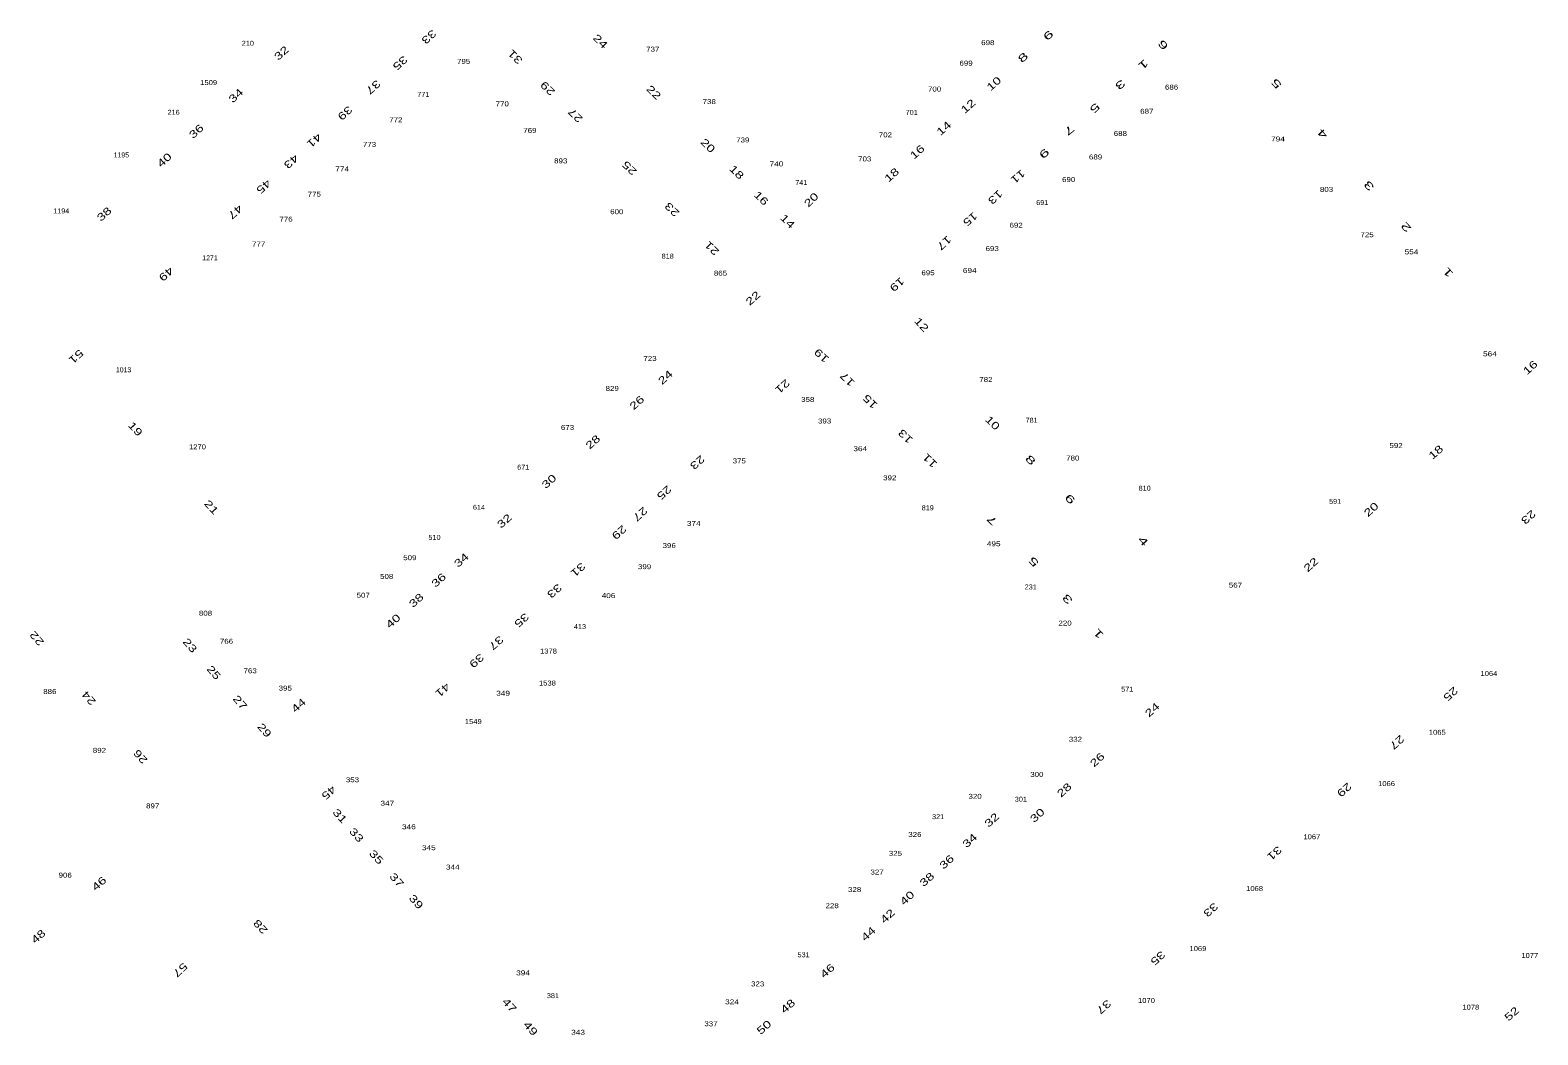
# Model space of a CAD drawing. Extents: x -828673 to -815583, y -1077737 to -1063807.
# Drawn here: x -819544.8 to -819239.5, y -1069308.8 to -1069105.5 of the extents above; entities that cross this region are included whole.
import ezdxf
from ezdxf.enums import TextEntityAlignment as Align

# ---------------------------------------------------------------- set-up
doc = ezdxf.new("R2010")
doc.units = 0
doc.header["$LTSCALE"] = 0.4
doc.layers.add('1', color=7, linetype='Continuous')
doc.layers.add('2', color=7, linetype='Continuous')

msp = doc.modelspace()

# ---------------------------------------------------------------- texts
at = {"layer": '1'}
for s, width, p in [('210', 1.1, (-819500.706, -1069108.652)), ('698', 1.2, (-819350.9, -1069108.522)), ('795', 1.2, (-819457.015, -1069112.317)), ('737', 1.2, (-819418.728, -1069109.841)), ('699', 1.2, (-819355.307, -1069112.674)), ('1509', 1.15, (-819508.639, -1069116.6)), ('700', 1.2, (-819361.669, -1069117.919)), ('686', 1.2, (-819313.692, -1069117.524)), ('771', 1.1, (-819465.18, -1069118.996)), ('770', 1.2, (-819449.199, -1069120.902)), ('738', 1.2, (-819407.298, -1069120.455)), ('216', 1.1, (-819515.726, -1069122.614)), ('772', 1.2, (-819470.741, -1069124.129)), ('701', 1.1, (-819366.311, -1069122.639)), ('687', 1.2, (-819318.711, -1069122.414)), ('769', 1.2, (-819443.605, -1069126.287)), ('702', 1.2, (-819371.637, -1069127.181)), ('688', 1.2, (-819324.064, -1069126.904)), ('773', 1.2, (-819476.07, -1069129.117)), ('739', 1.2, (-819400.501, -1069128.22)), ('794', 1.25, (-819292.15, -1069128.019)), ('1195', 1.05, (-819526.311, -1069131.255)), ('893', 1.2, (-819437.357, -1069132.45)), ('740', 1.25, (-819393.682, -1069133.057)), ('703', 1.2, (-819375.822, -1069132.053)), ('689', 1.2, (-819329.083, -1069131.66)), ('774', 1.25, (-819481.611, -1069134.077)), ('741', 1.1, (-819388.661, -1069136.838)), ('690', 1.2, (-819334.526, -1069136.227)), ('775', 1.2, (-819487.249, -1069139.182)), ('803', 1.2, (-819282.317, -1069138.219)), ('1194', 1.1, (-819538.478, -1069142.581)), ('600', 1.2, (-819426.009, -1069142.742)), ('691', 1.1, (-819339.878, -1069140.884)), ('776', 1.2, (-819492.975, -1069144.249)), ('692', 1.2, (-819345.164, -1069145.474)), ('725', 1.2, (-819274.121, -1069147.392)), ('1271', 1.05, (-819508.369, -1069152.082)), ('777', 1.2, (-819498.515, -1069149.284)), ('818', 1.1, (-819415.705, -1069151.741)), ('693', 1.2, (-819350.017, -1069150.197)), ('554', 1.25, (-819265.122, -1069150.858)), ('865', 1.2, (-819405.022, -1069155.175)), ('695', 1.2, (-819363.005, -1069155.103)), ('694', 1.25, (-819354.561, -1069154.637)), ('723', 1.2, (-819419.286, -1069172.445)), ('564', 1.25, (-819249.248, -1069171.499)), ('1013', 1.05, (-819525.868, -1069174.736)), ('829', 1.2, (-819426.936, -1069178.499)), ('782', 1.2, (-819351.279, -1069176.694)), ('358', 1.2, (-819387.35, -1069180.733)), ('393', 1.2, (-819383.941, -1069185.098)), ('781', 1.1, (-819342.037, -1069184.943)), ('673', 1.2, (-819435.977, -1069186.404)), ('1270', 1.15, (-819510.897, -1069190.316)), ('364', 1.25, (-819376.725, -1069190.701)), ('592', 1.2, (-819268.246, -1069190.071)), ('671', 1.1, (-819444.954, -1069194.447)), ('375', 1.2, (-819401.216, -1069193.173)), ('780', 1.2, (-819333.693, -1069192.593)), ('392', 1.2, (-819370.753, -1069196.594)), ('810', 1.1, (-819319.144, -1069198.693)), ('614', 1.1, (-819453.916, -1069202.565)), ('819', 1.1, (-819363.063, -1069202.678)), ('591', 1.1, (-819280.583, -1069201.357)), ('374', 1.25, (-819410.433, -1069205.832)), ('510', 1.1, (-819462.919, -1069208.651)), ('495', 1.25, (-819349.712, -1069209.944)), ('509', 1.2, (-819467.904, -1069212.763)), ('396', 1.2, (-819415.396, -1069210.306)), ('399', 1.2, (-819420.383, -1069214.584)), ('508', 1.2, (-819472.597, -1069216.556)), ('231', 1.1, (-819342.217, -1069218.688)), ('567', 1.2, (-819300.764, -1069218.329)), ('507', 1.2, (-819477.343, -1069220.35)), ('406', 1.25, (-819427.682, -1069220.433)), ('808', 1.2, (-819509.273, -1069223.997)), ('413', 1.1, (-819433.463, -1069226.708)), ('220', 1.2, (-819335.264, -1069225.999)), ('766', 1.2, (-819505.031, -1069229.674)), ('1378', 1.15, (-819439.842, -1069231.662)), ('763', 1.2, (-819500.234, -1069235.66)), ('1064', 1.15, (-819249.447, -1069236.205)), ('886', 1.2, (-819540.788, -1069239.847)), ('395', 1.2, (-819493.129, -1069239.162)), ('349', 1.25, (-819449.026, -1069240.193)), ('1538', 1.15, (-819440.054, -1069238.131)), ('571', 1.1, (-819322.672, -1069239.378)), ('1549', 1.15, (-819455.07, -1069245.928)), ('332', 1.2, (-819333.165, -1069249.505)), ('1065', 1.15, (-819259.896, -1069248.098)), ('892', 1.2, (-819530.75, -1069251.753)), ('353', 1.2, (-819479.525, -1069257.707)), ('300', 1.2, (-819340.964, -1069256.625)), ('1066', 1.15, (-819270.178, -1069258.477)), ('320', 1.2, (-819353.47, -1069261.062)), ('301', 1.1, (-819344.209, -1069261.645)), ('897', 1.2, (-819519.965, -1069262.993)), ('347', 1.25, (-819472.462, -1069262.454)), ('346', 1.25, (-819468.099, -1069267.229)), ('321', 1.1, (-819360.967, -1069265.176)), ('326', 1.2, (-819365.657, -1069268.777)), ('1067', 1.15, (-819285.299, -1069269.24)), ('345', 1.25, (-819464.064, -1069271.457)), ('325', 1.2, (-819369.611, -1069272.597)), ('906', 1.2, (-819537.684, -1069277.014)), ('344', 1.25, (-819459.216, -1069275.371)), ('327', 1.2, (-819373.32, -1069276.389)), ('328', 1.2, (-819377.863, -1069279.919)), ('1068', 1.15, (-819296.889, -1069279.722)), ('228', 1.2, (-819382.417, -1069283.193)), ('1069', 1.15, (-819308.365, -1069291.872)), ('531', 1.1, (-819388.198, -1069293.124)), ('1077', 1.15, (-819241.178, -1069293.275)), ('394', 1.25, (-819444.993, -1069296.789)), ('381', 1.1, (-819438.939, -1069301.4)), ('323', 1.2, (-819397.484, -1069299.021)), ('324', 1.25, (-819402.693, -1069302.65)), ('1070', 1.15, (-819318.776, -1069302.379)), ('1078', 1.15, (-819253.116, -1069303.73)), ('337', 1.2, (-819406.943, -1069307.088)), ('343', 1.25, (-819433.846, -1069308.81))]:
    msp.add_text(s, height=1, dxfattribs=dict(at, width=width)).set_placement(p, align=Align.CENTER)
at = {"layer": '2'}
for s, rotation, width, p in [('33', 222.205, 1.4, (-819464.5367, -1069106.3148)), ('24', 315.75, 1.4, (-819429.8553, -1069108.2929)), ('6', 41.825, 1.75, (-819338.1606, -1069107.1071)), ('6', 131.725, 1.75, (-819314.8655, -1069107.9997)), ('32', 42.334, 1.4, (-819493.3941, -1069110.677)), ('35', 222.177, 1.4, (-819470.3694, -1069111.5945)), ('31', 135.298, 1.4, (-819446.0509, -1069110.3945)), ('8', 41.987, 1.75, (-819343.2842, -1069111.5718)), ('1', 222, 1.75, (-819319.8927, -1069111.8994)), ('34', 42.713, 1.4, (-819502.6212, -1069119.2838)), ('37', 222.176, 1.4, (-819475.8224, -1069116.4825)), ('29', 136.01, 1.4, (-819439.4921, -1069116.7487)), ('22', 315.822, 1.4, (-819419.0507, -1069118.6198)), ('10', 41.781, 1.4, (-819349.1782, -1069116.8682)), ('3', 220.752, 1.75, (-819324.5624, -1069115.9774)), ('5', 132.373, 1.75, (-819291.9297, -1069115.823)), ('12', 41.653, 1.4, (-819354.392, -1069121.4458)), ('5', 223.476, 1.75, (-819329.7385, -1069120.7226)), ('39', 222.162, 1.4, (-819481.5216, -1069121.7351)), ('27', 135.745, 1.4, (-819433.8796, -1069122.22)), ('36', 42.096, 1.4, (-819510.6413, -1069126.5233)), ('41', 222.202, 1.4, (-819487.7647, -1069127.2737)), ('14', 41.875, 1.4, (-819359.3126, -1069125.9081)), ('7', 220.045, 1.75, (-819334.904, -1069125.1842)), ('4', 132.265, 1.75, (-819282.6026, -1069125.9794)), ('20', 315.69, 1.4, (-819408.0784, -1069129.3871)), ('16', 42.163, 1.4, (-819364.6914, -1069130.7019)), ('9', 223.307, 1.75, (-819340.0016, -1069129.9107)), ('40', 42.174, 1.4, (-819517.1035, -1069132.3266)), ('43', 222.17, 1.4, (-819492.4185, -1069131.5453)), ('25', 135.669, 1.4, (-819422.9284, -1069132.8843)), ('45', 222.129, 1.4, (-819497.9874, -1069136.6126)), ('18', 315.67, 1.4, (-819402.2656, -1069134.7677)), ('18', 41.696, 1.4, (-819369.8639, -1069135.3501)), ('11', 220.426, 1.35, (-819345.2607, -1069134.5673)), ('16', 315.718, 1.4, (-819397.2996, -1069140.0358)), ('20', 44.904, 1.4, (-819386.1204, -1069140.3621)), ('13', 223.118, 1.4, (-819349.8739, -1069138.7518)), ('3', 132.545, 1.75, (-819273.1836, -1069136.5071)), ('38', 42.263, 1.4, (-819529.2844, -1069143.259)), ('47', 222.218, 1.4, (-819503.7385, -1069141.7332)), ('23', 135.98, 1.4, (-819414.3213, -1069141.2753)), ('14', 315.798, 1.4, (-819391.9474, -1069144.704)), ('15', 220.727, 1.35, (-819354.9387, -1069143.1858)), ('2', 132.34, 1.75, (-819265.6622, -1069144.8756)), ('17', 222.872, 1.4, (-819360.2372, -1069148.0128)), ('21', 135.71, 1.4, (-819406.2583, -1069149.106)), ('49', 221.844, 1.4, (-819517.7292, -1069154.3125)), ('1', 132.358, 1.75, (-819257.1839, -1069154.0423)), ('19', 221.566, 1.4, (-819369.7509, -1069156.4148)), ('22', 41.944, 1.4, (-819397.9428, -1069160.2926)), ('12', 312.243, 1.4, (-819364.8781, -1069165.5743)), ('51', 222.715, 1.4, (-819535.9697, -1069171.0173)), ('19', 137.273, 1.4, (-819384.0641, -1069170.8199)), ('16', 42.155, 1.4, (-819240.5834, -1069174.3241)), ('24', 41.835, 1.4, (-819415.6747, -1069176.3097)), ('17', 135.668, 1.4, (-819378.8214, -1069175.6332)), ('21', 222.023, 1.4, (-819392.9589, -1069177.0532)), ('26', 41.991, 1.4, (-819421.4468, -1069181.4408)), ('15', 135.44, 1.4, (-819374.1948, -1069180.1441)), ('10', 315.665, 1.4, (-819350.4636, -1069185.5148)), ('19', 312.746, 1.4, (-819524.0183, -1069186.6989)), ('28', 41.796, 1.4, (-819430.3554, -1069189.4008)), ('13', 135.948, 1.4, (-819367.0525, -1069187.1859)), ('18', 41.489, 1.4, (-819259.7034, -1069191.4664)), ('23', 221.586, 1.4, (-819410.1807, -1069192.4304)), ('11', 135.4, 1.4, (-819362.1049, -1069192.1045)), ('8', 315.767, 1.75, (-819342.7812, -1069193.0352)), ('30', 41.753, 1.4, (-819439.2359, -1069197.375)), ('25', 222.214, 1.4, (-819416.9156, -1069198.5451)), ('6', 315.985, 1.75, (-819334.7806, -1069200.9305)), ('21', 312.7, 1.4, (-819508.6232, -1069202.5449)), ('27', 222.068, 1.4, (-819421.7705, -1069202.8824)), ('20', 42.365, 1.4, (-819272.7824, -1069203.0422)), ('23', 221.503, 1.4, (-819241.9345, -1069203.5019)), ('32', 41.792, 1.4, (-819448.2753, -1069205.3829)), ('29', 221.813, 1.4, (-819426.023, -1069206.5922)), ('7', 135.55, 1.75, (-819349.5458, -1069204.1696)), ('4', 312.057, 1.75, (-819319.9808, -1069209.3981)), ('34', 41.728, 1.4, (-819456.9882, -1069213.3022)), ('5', 132.258, 1.75, (-819341.0731, -1069212.5969)), ('31', 221.854, 1.4, (-819434.3461, -1069214.1488)), ('22', 42.392, 1.4, (-819284.9791, -1069214.2229)), ('36', 41.586, 1.4, (-819461.5743, -1069217.3626)), ('33', 221.975, 1.4, (-819439.1194, -1069218.4538)), ('38', 41.783, 1.4, (-819466.1082, -1069221.4461)), ('3', 132.224, 1.75, (-819334.2266, -1069220.1545)), ('40', 41.696, 1.4, (-819470.7929, -1069225.6281)), ('35', 221.86, 1.4, (-819445.7725, -1069224.3725)), ('22', 131.172, 1.4, (-819542.8757, -1069228.1262)), ('1', 132.357, 1.75, (-819327.9429, -1069227.1793)), ('23', 311.25, 1.4, (-819512.9856, -1069230.4965)), ('37', 221.745, 1.4, (-819450.9221, -1069228.9568)), ('39', 221.57, 1.4, (-819454.8728, -1069232.5629)), ('25', 311.223, 1.35, (-819508.1604, -1069235.9898)), ('24', 131.145, 1.35, (-819532.3489, -1069240.189)), ('41', 221.513, 1.4, (-819461.7509, -1069238.4918)), ('25', 222.096, 1.4, (-819257.6957, -1069239.2977)), ('27', 311.193, 1.4, (-819502.8348, -1069242.0546)), ('44', 41.894, 1.4, (-819489.9468, -1069242.7145)), ('24', 42.017, 1.4, (-819317.116, -1069243.606)), ('29', 311.222, 1.35, (-819497.9024, -1069247.6788)), ('27', 222.148, 1.4, (-819268.5547, -1069249.0837)), ('26', 131.139, 1.35, (-819521.8908, -1069252.0439)), ('26', 42.803, 1.4, (-819328.2381, -1069253.7052)), ('28', 42.468, 1.4, (-819334.9184, -1069259.8182)), ('29', 222.138, 1.4, (-819279.2233, -1069258.6929)), ('45', 221.285, 1.35, (-819484.8096, -1069259.2579)), ('31', 312.274, 1.4, (-819482.6117, -1069265.0295)), ('32', 42.438, 1.4, (-819349.5851, -1069265.8971)), ('30', 42.129, 1.4, (-819340.3796, -1069264.9594)), ('33', 311.805, 1.4, (-819479.269, -1069268.879)), ('34', 41.92, 1.4, (-819354.0556, -1069270.0743)), ('35', 312.499, 1.4, (-819475.2278, -1069273.3488)), ('36', 42.678, 1.4, (-819358.7209, -1069274.3808)), ('31', 222.077, 1.4, (-819293.3694, -1069271.5426)), ('37', 311.735, 1.4, (-819471.122, -1069278.0017)), ('38', 41.616, 1.4, (-819362.7271, -1069277.9334)), ('46', 41.318, 1.4, (-819530.3367, -1069278.7652)), ('39', 311.696, 1.4, (-819467.1941, -1069282.3951)), ('40', 43.287, 1.4, (-819366.7292, -1069281.6769)), ('33', 222.068, 1.4, (-819306.2605, -1069282.9844)), ('42', 43.241, 1.4, (-819370.6993, -1069285.3427)), ('48', 41.285, 1.35, (-819542.6324, -1069289.4741)), ('28', 131.973, 1.4, (-819497.5997, -1069286.4536)), ('44', 42.277, 1.4, (-819374.5965, -1069288.9486)), ('57', 223.328, 1.4, (-819514.9014, -1069295.1453)), ('46', 41.396, 1.4, (-819382.8849, -1069296.4285)), ('35', 222.057, 1.4, (-819316.9656, -1069292.7451)), ('47', 311.849, 1.4, (-819448.2973, -1069303.3311)), ('48', 41.536, 1.4, (-819390.8913, -1069303.5846)), ('37', 222.036, 1.4, (-819327.9153, -1069302.636)), ('52', 42.129, 1.4, (-819244.3276, -1069305.1314)), ('49', 311.968, 1.4, (-819444.0139, -1069308.023)), ('50', 41.367, 1.4, (-819395.7167, -1069307.8673))]:
    msp.add_text(s, height=1.5, rotation=rotation, dxfattribs=dict(at, width=width)).set_placement(p, align=Align.CENTER)

doc.saveas('drawing.dxf')
